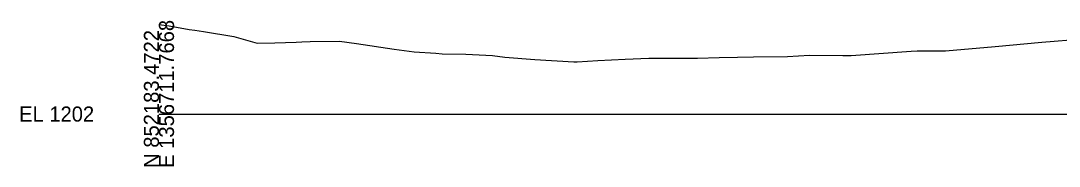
# Model space of a CAD drawing. Extents: x -26 to 3203, y -10 to 4066.
# Drawn here: x -25.7 to 167.4, y 2990.3 to 3017.3 of the extents above; entities that cross this region are included whole.
import ezdxf

# ---------------------------------------------------------------- set-up
doc = ezdxf.new("R2010")
doc.units = 0
doc.layers.add('Exist Cross Section Cell', color=7, linetype='Continuous')
doc.layers.add('Exist XS Ground Line', color=7, linetype='Continuous')

msp = doc.modelspace()

# ---------------------------------------------------------------- linework, layer by layer
at = {"layer": 'Exist Cross Section Cell'}
msp.add_line((0, 3000), (200, 3000), dxfattribs=at)
at = {"layer": 'Exist XS Ground Line'}
for p, q in [((0, 3016.61), (1.88, 3016.37)), ((1.88, 3016.37), (5.63, 3015.69)), ((5.63, 3015.69), (6.7, 3015.57)), ((6.7, 3015.57), (8.29, 3015.32)), ((8.29, 3015.32), (13.93, 3014.39)), ((13.93, 3014.39), (18.26, 3013.15)), ((164.2, 3013.37), (182.38, 3014.76)), ((18.26, 3013.15), (21.54, 3013.23)), ((21.54, 3013.23), (25.5, 3013.38)), ((25.5, 3013.38), (26.6, 3013.42)), ((26.6, 3013.42), (28.1, 3013.48)), ((28.1, 3013.48), (33.56, 3013.52)), ((33.56, 3013.52), (36.75, 3013.09)), ((36.75, 3013.09), (43.74, 3012.06)), ((146.25, 3011.72), (155.52, 3012.57)), ((155.52, 3012.57), (164.2, 3013.37)), ((43.74, 3012.06), (47.48, 3011.56)), ((47.48, 3011.56), (51.48, 3011.32)), ((51.48, 3011.32), (52.65, 3011.2)), ((52.65, 3011.2), (57.06, 3011.1)), ((57.06, 3011.1), (62, 3010.85)), ((62, 3010.85), (64.29, 3010.54)), ((64.29, 3010.54), (69.91, 3010.12)), ((100.15, 3010.4), (104.17, 3010.48)), ((104.17, 3010.48), (107.61, 3010.55)), ((107.61, 3010.55), (110.58, 3010.65)), ((110.58, 3010.65), (116.9, 3010.71)), ((116.9, 3010.71), (120.96, 3010.92)), ((120.96, 3010.92), (127.18, 3010.85)), ((127.18, 3010.85), (128.72, 3010.86)), ((128.72, 3010.86), (139.88, 3011.67)), ((139.88, 3011.67), (140.97, 3011.71)), ((140.97, 3011.71), (141.94, 3011.71)), ((141.94, 3011.71), (146.25, 3011.72)), ((69.91, 3010.12), (77.13, 3009.72)), ((77.13, 3009.72), (77.78, 3009.69)), ((77.78, 3009.69), (81.59, 3009.92)), ((81.59, 3009.92), (86.7, 3010.21)), ((86.7, 3010.21), (91.09, 3010.39)), ((91.09, 3010.39), (100.15, 3010.4))]:
    msp.add_line(p, q, dxfattribs=at)

# ---------------------------------------------------------------- texts
at = {"layer": 'Exist Cross Section Cell'}
for s, p in [('E 1356711.7668', (2.8, 2990)), ('N 852183.4722', (0, 2990))]:
    msp.add_text(s, height=2.8, rotation=90, dxfattribs=at).set_placement(p)
msp.add_text('EL 1202', height=2.8, dxfattribs=at).set_placement((-26, 2998.6))

doc.saveas('drawing.dxf')
